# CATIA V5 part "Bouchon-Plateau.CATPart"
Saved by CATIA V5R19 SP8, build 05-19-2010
Part number: Bouchon-Plateau
Nomenclature: 42
Material "Plastique": density 1200 kg/m3, Young's modulus 2.2e+09 Pa, Poisson ratio 0.38, thermal expansion 6.84e-05 1/K
Bounding box of the stored display mesh (mm): x -12.5 to 12.5, y -4 to 6.5, z -25 to 25
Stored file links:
  C:\Users\rphgr\Desktop\0_Tapis_TC520B_vitesse\Bouchon-Plateau.CATPart
  D:\Documents\1_Travail\1 - ac-limoges.fr\ac-limoges.fr\Emmanuel Maynard - STI2D_Turgot\3 - Supports\Tapis de course TC520B\Tapis de course TC520B_Ca\0_Tapis_TC520B.CATProduct
  D:\Documents\1_Travail\1 - ac-limoges.fr\ac-limoges.fr\Emmanuel Maynard - STI2D_Turgot\3 - Supports\Tapis de course TC520B\Tapis de course TC520B_Ca\Cadre Plateau.CATPart
  D:\Programmes\DassaultSysteme\win_b64\startup\materials\French\Catalog.CATMaterial
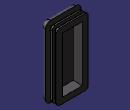
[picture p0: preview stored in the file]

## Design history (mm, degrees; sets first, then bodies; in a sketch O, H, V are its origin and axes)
AxisSystem1: origin (0, 0, 0), X (1, 0, 0), Y (0, 1, 0), Z (0, 0, 1)
Body1 (main body), material "Plastique"
  Sketch1 on zx-plane, origin (0, 0, 0), H (-1, 0, 0), V (0, 0, 1)
    line L1 (9, 21.5) -> (9, -21.5)
    line L2 (9, -21.5) -> (-9, -21.5)
    line L3 (-9, -21.5) -> (-9, 21.5)
    line L4 (-9, 21.5) -> (9, 21.5)
    line L5 (7, 19.5) -> (7, -19.5)
    line L6 (7, -19.5) -> (-7, -19.5)
    line L7 (-7, -19.5) -> (-7, 19.5)
    line L8 (-7, 19.5) -> (7, 19.5)
    distance L1 L3 = 18
    distance L4 L2 = 43
    distance L7 L5 = 14
    distance L8 L6 = 39
    vertical: L1 V, L3 V, L5 V, L7 V
    horizontal: L2 H, L4 H, L6 H, L8 H
    equidistance: L1 L3 O, L2 L4 O, L5 L7 O, L6 L8 O
  Pad1: profile Sketch1, direction (0, 1, 0), length 6.5
  Sketch2 on start face of Pad1, origin (0, 0, 0), H (1, 0, 0), V (0, 0, 1)
  Pad2: profile Sketch2, direction (0, -1, 0), length 4
  Fillet1: radius 4, on end face of Pad2
  Sketch3 on end face of Pad1, origin (0, 6.5, 0), H (-1, 0, 0), V (0, 0, 1)
    line L1 (9, 21.5) -> (9, -21.5)
    line L2 (9, -21.5) -> (-9, -21.5)
    line L3 (-9, -21.5) -> (-9, 21.5)
    line L4 (-9, 21.5) -> (9, 21.5)
    reference projected line E2 (9, 21.5) -> (-9, 21.5) from edge [face of Pad1 from Sketch1.L4 | end face of Pad1]
    reference projected line E3 (9, -21.5) -> (9, 21.5) from edge [face of Pad1 from Sketch1.L1 | end face of Pad1]
    vertical: L1 V, L3 V
    horizontal: L2 H, L4 H
    equidistance: L1 L3 O, L2 L4 O
    coincidence: L4 E2, L1 E3
  Pad3: profile Sketch3, direction (0, -1, 0), length 1
  RectPattern1: of Pad3, direction 1 instances 2, spacing 3.25, along edge [face of Pad1 from Sketch1.L2 | face of Pad1 from Sketch1.L3] reversed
